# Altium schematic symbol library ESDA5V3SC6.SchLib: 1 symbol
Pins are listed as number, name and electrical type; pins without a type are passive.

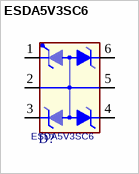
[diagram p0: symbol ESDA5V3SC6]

## ESDA5V3SC6
designator D?
footprint ST_SOT23-6L
pins: 1, 2, 3, 4, 5, 6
